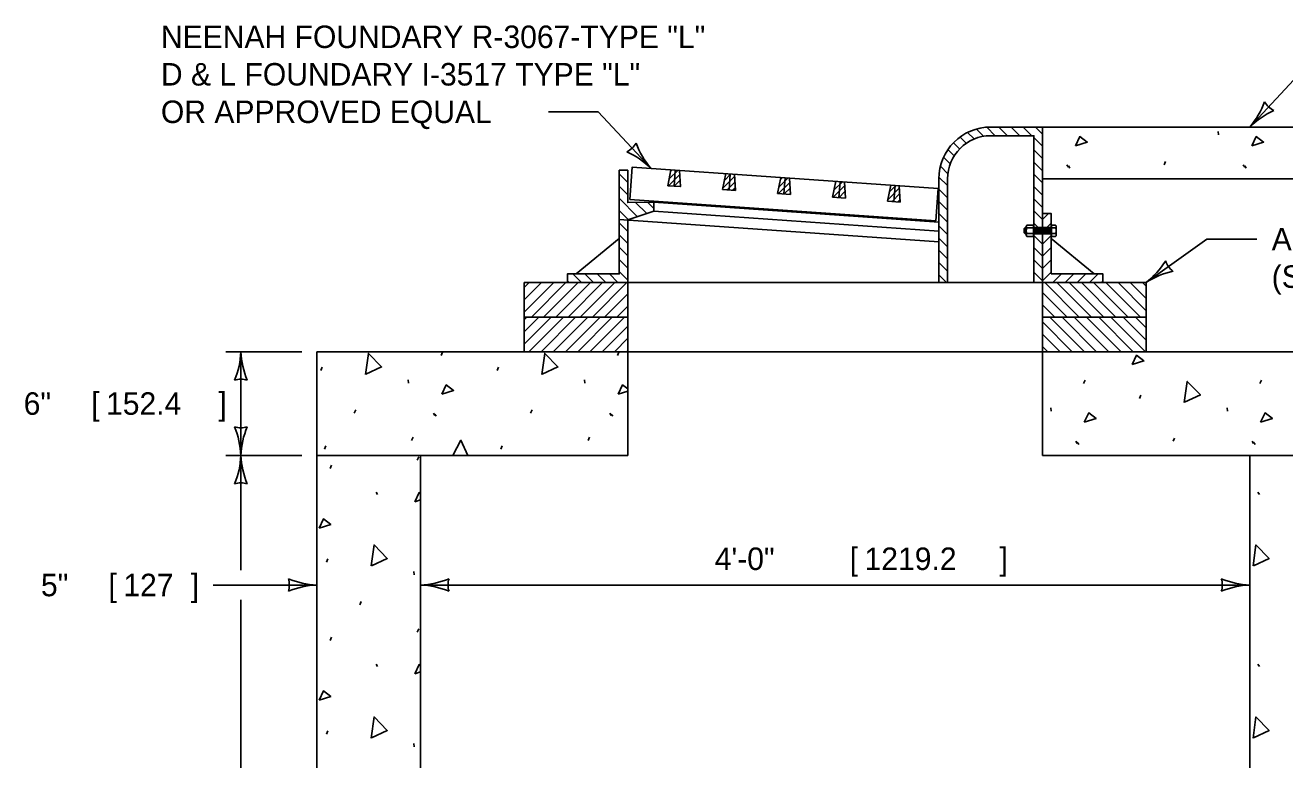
# Model space of a CAD drawing. Extents: x 49991.4 to 50057, y 49987.6 to 50011.4.
# Drawn here: x 50041.919 to 50045.28, y 49991.034 to 49992.994 of the extents above; entities that cross this region are included whole.
import ezdxf

# ---------------------------------------------------------------- set-up
doc = ezdxf.new("R2010")
doc.units = 0
for name, color, linetype in [('Level 1', 7, 'Continuous'), ('Level 2', 7, 'Continuous'), ('Level 3', 7, 'Continuous'), ('Level 4', 7, 'Continuous'), ('Level 5', 7, 'Continuous')]:
    doc.layers.add(name, color=color, linetype=linetype)

msp = doc.modelspace()

# ---------------------------------------------------------------- linework, layer by layer
at = {"layer": 'Level 1'}
for p, q in [((50044.4336, 49992.7076), (50044.451, 49992.6902)), ((50044.4571, 49992.7167), (50044.4763, 49992.6975)), ((50044.4847, 49992.7217), (50044.5074, 49992.699)), ((50044.5169, 49992.722), (50044.54, 49992.699)), ((50044.5495, 49992.722), (50044.5726, 49992.699)), ((50044.5821, 49992.722), (50044.6052, 49992.699)), ((50044.6147, 49992.722), (50044.6334, 49992.7034)), ((50044.6334, 49992.722), (50045.7396, 49992.722)), ((50045.102, 49992.7102), (50045.103, 49992.7014)), ((50044.3959, 49992.6801), (50044.4122, 49992.6638)), ((50044.4133, 49992.6953), (50044.4299, 49992.6788)), ((50044.6103, 49992.6939), (50044.6334, 49992.6708)), ((50044.3694, 49992.6414), (50044.387, 49992.6238)), ((50044.3812, 49992.6622), (50044.3978, 49992.6456)), ((50044.6103, 49992.6613), (50044.6334, 49992.6382)), ((50043.6421, 49992.6082), (50043.6334, 49992.5655)), ((50043.6369, 49992.5828), (50043.661, 49992.6069)), ((50043.6411, 49992.6033), (50043.6458, 49992.608)), ((50043.6651, 49992.6066), (50043.6678, 49992.5631)), ((50044.3609, 49992.6173), (50044.3807, 49992.5976)), ((50044.6103, 49992.6287), (50044.6334, 49992.6056)), ((50044.6985, 49992.6209), (50044.7024, 49992.615)), ((50044.7024, 49992.6187), (50044.7064, 49992.6128)), ((50044.9579, 49992.6209), (50044.9618, 49992.6298)), ((50045.1691, 49992.6209), (50045.173, 49992.615)), ((50045.173, 49992.6187), (50045.1769, 49992.6128)), ((50043.5041, 49992.5973), (50043.5271, 49992.5743)), ((50043.6358, 49992.5654), (50043.6658, 49992.5954)), ((50043.651, 49992.5643), (50043.6668, 49992.5801)), ((50043.7887, 49992.598), (50043.7799, 49992.5553)), ((50043.7807, 49992.5591), (50043.812, 49992.5905)), ((50043.7849, 49992.5796), (50043.8023, 49992.597)), ((50043.7923, 49992.5544), (50043.813, 49992.5751)), ((50043.8117, 49992.5964), (50043.8144, 49992.5529)), ((50043.9352, 49992.5877), (50043.9265, 49992.545)), ((50043.9293, 49992.5448), (50043.959, 49992.5745)), ((50043.9299, 49992.5618), (50043.9545, 49992.5864)), ((50043.9341, 49992.5823), (50043.9393, 49992.5874)), ((50043.9582, 49992.5861), (50043.961, 49992.5426)), ((50044.0818, 49992.5775), (50044.073, 49992.5348)), ((50044.0768, 49992.5533), (50044.0998, 49992.5762)), ((50044.081, 49992.5738), (50044.0846, 49992.5773)), ((50044.1048, 49992.5759), (50044.1075, 49992.5324)), ((50044.3569, 49992.5888), (50044.3799, 49992.5658)), ((50044.6103, 49992.5961), (50044.6334, 49992.573)), ((50044.6334, 49992.5838), (50045.7396, 49992.5838)), ((50043.5041, 49992.5647), (50043.5271, 49992.5417)), ((50043.6334, 49992.5655), (50043.6678, 49992.5631)), ((50043.6662, 49992.5632), (50043.6677, 49992.5648)), ((50043.7799, 49992.5553), (50043.8144, 49992.5529)), ((50043.8075, 49992.5533), (50043.814, 49992.5598)), ((50043.9265, 49992.545), (50043.961, 49992.5426)), ((50043.9445, 49992.5438), (50043.9599, 49992.5592)), ((50043.9597, 49992.5427), (50043.9609, 49992.5438)), ((50044.0745, 49992.5347), (50044.1054, 49992.5656)), ((50044.0898, 49992.5336), (50044.1064, 49992.5502)), ((50044.2284, 49992.5672), (50044.2196, 49992.5245)), ((50044.2204, 49992.5283), (50044.2517, 49992.5597)), ((50044.2246, 49992.5488), (50044.242, 49992.5663)), ((50044.232, 49992.5237), (50044.2527, 49992.5444)), ((50044.2514, 49992.5656), (50044.2541, 49992.5221)), ((50044.3568, 49992.5563), (50044.3799, 49992.5332)), ((50044.6103, 49992.5635), (50044.6334, 49992.5404)), ((50043.5041, 49992.5321), (50043.5532, 49992.483)), ((50043.548, 49992.5208), (50043.5777, 49992.4911)), ((50043.58, 49992.5213), (50043.5963, 49992.5051)), ((50043.5963, 49992.5216), (50043.5963, 49992.5216)), ((50043.5963, 49992.5216), (50044.3568, 49992.4685)), ((50044.073, 49992.5348), (50044.1075, 49992.5324)), ((50044.105, 49992.5325), (50044.1074, 49992.5349)), ((50044.2196, 49992.5245), (50044.2541, 49992.5221)), ((50044.2472, 49992.5226), (50044.2537, 49992.529)), ((50044.3568, 49992.5237), (50044.3799, 49992.5006)), ((50044.6103, 49992.5309), (50044.6334, 49992.5079)), ((50043.5041, 49992.4995), (50043.5288, 49992.4748)), ((50043.5041, 49992.4759), (50044.3568, 49992.4163)), ((50043.5963, 49992.4973), (50044.3568, 49992.4442)), ((50044.3568, 49992.4911), (50044.3799, 49992.468)), ((50044.6103, 49992.4983), (50044.6334, 49992.4753)), ((50044.6334, 49992.4752), (50044.6498, 49992.4916)), ((50043.5041, 49992.4669), (50043.5271, 49992.4439)), ((50044.3568, 49992.4585), (50044.3799, 49992.4354)), ((50044.5841, 49992.4513), (50044.587, 49992.4541)), ((50044.5841, 49992.4513), (50044.5841, 49992.4397)), ((50044.5841, 49992.4397), (50044.587, 49992.4369)), ((50044.5855, 49992.4513), (50044.5855, 49992.4397)), ((50044.587, 49992.4541), (50044.587, 49992.4369)), ((50044.5898, 49992.4541), (50044.587, 49992.4541)), ((50044.5884, 49992.4513), (50044.5884, 49992.4397)), ((50044.5898, 49992.4343), (50044.5898, 49992.4567)), ((50044.6096, 49992.4605), (50044.5918, 49992.4605)), ((50044.6096, 49992.453), (50044.5918, 49992.453)), ((50044.6096, 49992.438), (50044.5918, 49992.438)), ((50044.6096, 49992.4305), (50044.6096, 49992.4605)), ((50044.6103, 49992.4585), (50044.6096, 49992.4585)), ((50044.6103, 49992.4657), (50044.6334, 49992.4427)), ((50044.6103, 49992.4325), (50044.6103, 49992.4585)), ((50044.6334, 49992.4426), (50044.6564, 49992.4656)), ((50044.6564, 49992.4325), (50044.6564, 49992.4585)), ((50044.6564, 49992.4585), (50044.6571, 49992.4585)), ((50044.6571, 49992.4605), (50044.668, 49992.4605)), ((50044.6571, 49992.4305), (50044.6571, 49992.4605)), ((50044.6571, 49992.453), (50044.668, 49992.453)), ((50044.6571, 49992.438), (50044.668, 49992.438)), ((50044.67, 49992.4343), (50044.67, 49992.4567)), ((50043.5041, 49992.4248), (50043.3889, 49992.3303)), ((50043.5041, 49992.4343), (50043.5271, 49992.4113)), ((50044.3568, 49992.4259), (50044.3799, 49992.4028)), ((50044.5898, 49992.4369), (50044.587, 49992.4369)), ((50044.6096, 49992.4305), (50044.5918, 49992.4305)), ((50044.6103, 49992.4325), (50044.6096, 49992.4325)), ((50044.6103, 49992.4331), (50044.6334, 49992.4101)), ((50044.6334, 49992.41), (50044.6564, 49992.4331)), ((50044.6564, 49992.4325), (50044.6571, 49992.4325)), ((50044.6564, 49992.4248), (50044.7716, 49992.3303)), ((50044.6571, 49992.4305), (50044.668, 49992.4305)), ((50043.5041, 49992.4017), (50043.5271, 49992.3787)), ((50044.3568, 49992.3933), (50044.3799, 49992.3703)), ((50044.6103, 49992.4005), (50044.6334, 49992.3775)), ((50044.6334, 49992.3774), (50044.6564, 49992.4005)), ((50043.5041, 49992.3692), (50043.5271, 49992.3461)), ((50044.3568, 49992.3607), (50044.3799, 49992.3377)), ((50044.6103, 49992.3679), (50044.6334, 49992.3449)), ((50044.6334, 49992.3448), (50044.6564, 49992.3679)), ((50043.2506, 49992.2285), (50043.3293, 49992.3072)), ((50043.2506, 49992.2611), (50043.2967, 49992.3072)), ((50043.2506, 49992.2937), (50043.2641, 49992.3072)), ((50043.2697, 49992.215), (50043.3619, 49992.3072)), ((50043.3023, 49992.215), (50043.3945, 49992.3072)), ((50043.3349, 49992.215), (50043.4271, 49992.3072)), ((50043.3658, 49992.3119), (50043.3705, 49992.3072)), ((50043.3658, 49992.3119), (50043.3705, 49992.3072)), ((50043.3675, 49992.215), (50043.4596, 49992.3072)), ((50043.38, 49992.3303), (50043.4031, 49992.3072)), ((50043.4001, 49992.215), (50043.4922, 49992.3072)), ((50043.4126, 49992.3303), (50043.4357, 49992.3072)), ((50043.4326, 49992.215), (50043.5248, 49992.3072)), ((50043.4452, 49992.3303), (50043.4683, 49992.3072)), ((50043.4778, 49992.3303), (50043.5008, 49992.3072)), ((50043.5041, 49992.3366), (50043.5271, 49992.3135)), ((50043.5271, 49992.3072), (50044.6334, 49992.3072)), ((50043.5271, 49992.3072), (50044.6334, 49992.3072)), ((50044.3568, 49992.3281), (50044.3777, 49992.3072)), ((50044.6103, 49992.3353), (50044.6334, 49992.3123)), ((50044.6334, 49992.3122), (50044.6564, 49992.3353)), ((50044.6394, 49992.3072), (50044.7316, 49992.215)), ((50044.6609, 49992.3072), (50044.684, 49992.3303)), ((50044.672, 49992.3072), (50044.7642, 49992.215)), ((50044.6935, 49992.3072), (50044.7166, 49992.3303)), ((50044.7046, 49992.3072), (50044.7968, 49992.215)), ((50044.7261, 49992.3072), (50044.7492, 49992.3303)), ((50044.7372, 49992.3072), (50044.8294, 49992.215)), ((50044.7587, 49992.3072), (50044.7818, 49992.3303)), ((50044.7698, 49992.3072), (50044.862, 49992.215)), ((50044.7913, 49992.3072), (50044.7947, 49992.3106)), ((50044.7913, 49992.3072), (50044.7947, 49992.3106)), ((50044.8024, 49992.3072), (50044.8946, 49992.215)), ((50044.835, 49992.3072), (50044.9099, 49992.2323)), ((50044.8676, 49992.3072), (50044.9099, 49992.2649)), ((50044.9002, 49992.3072), (50044.9099, 49992.2975)), ((50043.4652, 49992.215), (50043.5271, 49992.2769)), ((50044.6334, 49992.2807), (50044.699, 49992.215)), ((50043.4978, 49992.215), (50043.5271, 49992.2444)), ((50044.6334, 49992.2481), (50044.6664, 49992.215)), ((50043.2506, 49992.143), (50043.3227, 49992.215)), ((50043.2506, 49992.1756), (50043.2901, 49992.215)), ((50043.2506, 49992.2082), (50043.2575, 49992.215)), ((50043.2631, 49992.1229), (50043.3552, 49992.215)), ((50043.2957, 49992.1229), (50043.3878, 49992.215)), ((50043.3282, 49992.1229), (50043.4204, 49992.215)), ((50043.3608, 49992.1229), (50043.453, 49992.215)), ((50043.3934, 49992.1229), (50043.4856, 49992.215)), ((50043.426, 49992.1229), (50043.5182, 49992.215)), ((50044.6334, 49992.2155), (50044.6339, 49992.215)), ((50044.6531, 49992.215), (50044.7453, 49992.1229)), ((50044.6857, 49992.215), (50044.7778, 49992.1229)), ((50044.7183, 49992.215), (50044.8104, 49992.1229)), ((50044.7508, 49992.215), (50044.843, 49992.1229)), ((50044.7834, 49992.215), (50044.8756, 49992.1229)), ((50044.816, 49992.215), (50044.9082, 49992.1229)), ((50044.8486, 49992.215), (50044.9099, 49992.1537)), ((50044.8812, 49992.215), (50044.9099, 49992.1863)), ((50043.4586, 49992.1229), (50043.5271, 49992.1914)), ((50044.6334, 49992.2022), (50044.7127, 49992.1229)), ((50044.6334, 49992.1696), (50044.6801, 49992.1229)), ((50043.4912, 49992.1229), (50043.5271, 49992.1588)), ((50044.6334, 49992.137), (50044.6475, 49992.1229)), ((50042.6975, 49989.6339), (50042.6975, 49992.1229)), ((50042.6975, 49992.1229), (50043.5271, 49992.1229)), ((50043.029, 49992.1128), (50043.0329, 49992.1217)), ((50043.4995, 49992.1128), (50043.5035, 49992.1217)), ((50043.5238, 49992.1229), (50043.5271, 49992.1262)), ((50043.5271, 49992.1229), (50043.5271, 49991.8463)), ((50043.5271, 49992.1229), (50044.6334, 49992.1229)), ((50044.6334, 49992.1229), (50045.463, 49992.1229)), ((50044.6334, 49992.1229), (50044.6334, 49991.8463)), ((50042.7077, 49992.0725), (50042.7117, 49992.0814)), ((50043.1783, 49992.0725), (50043.1822, 49992.0814)), ((50042.9413, 49992.0479), (50042.9423, 49992.039)), ((50043.4119, 49992.0479), (50043.4128, 49992.039)), ((50044.7429, 49992.038), (50044.7468, 49992.0468)), ((50045.2134, 49992.038), (50045.2173, 49992.0468)), ((50043.5271, 49992.0177), (50043.5015, 49992.0097)), ((50044.8922, 49991.9977), (50044.8961, 49992.0066)), ((50042.7971, 49991.9586), (50042.8011, 49991.9674)), ((50043.2677, 49991.9586), (50043.2716, 49991.9674)), ((50044.6552, 49991.973), (50044.6562, 49991.9642)), ((50045.1257, 49991.973), (50045.1267, 49991.9642)), ((50043.0084, 49991.9586), (50043.0123, 49991.9527)), ((50043.0123, 49991.9564), (50043.0162, 49991.9505)), ((50043.4789, 49991.9586), (50043.4828, 49991.9527)), ((50043.4828, 49991.9564), (50043.4868, 49991.9505)), ((50042.7176, 49991.8632), (50042.7215, 49991.872)), ((50042.9504, 49991.8858), (50042.9543, 49991.8946)), ((50043.1881, 49991.8632), (50043.1921, 49991.872)), ((50043.4209, 49991.8858), (50043.4249, 49991.8946)), ((50044.7222, 49991.8838), (50044.7261, 49991.8779)), ((50044.7261, 49991.8815), (50044.7301, 49991.8756)), ((50044.9816, 49991.8838), (50044.9855, 49991.8926)), ((50045.1928, 49991.8838), (50045.1967, 49991.8779)), ((50045.1967, 49991.8815), (50045.2006, 49991.8756)), ((50042.6975, 49991.8463), (50043.5271, 49991.8463)), ((50042.9654, 49991.8337), (50042.9693, 49991.8425)), ((50042.974, 49989.9104), (50042.974, 49991.8463)), ((50044.6334, 49991.8463), (50045.463, 49991.8463)), ((50045.1865, 49989.9104), (50045.1865, 49991.8463)), ((50042.7326, 49991.8111), (50042.7365, 49991.8199)), ((50042.8554, 49991.7482), (50042.8593, 49991.7423)), ((50045.2081, 49991.7482), (50045.2121, 49991.7423)), ((50042.974, 49991.7275), (50042.9585, 49991.7227)), ((50042.7228, 49991.5616), (50042.7267, 49991.5704)), ((50042.9563, 49991.5369), (50042.9573, 49991.5281)), ((50042.8121, 49991.4476), (50042.8161, 49991.4565)), ((50042.9654, 49991.3748), (50042.9693, 49991.3837)), ((50042.7326, 49991.3522), (50042.7365, 49991.3611)), ((50042.8554, 49991.2893), (50042.8593, 49991.2835)), ((50042.974, 49991.2687), (50042.9585, 49991.2638)), ((50045.2081, 49991.2893), (50045.2121, 49991.2835)), ((50042.7228, 49991.1027), (50042.7267, 49991.1115)), ((50042.9563, 49991.078), (50042.9573, 49991.0692))]:
    msp.add_line(p, q, dxfattribs=at)
for points in [[(50044.4951, 49992.699), (50044.6103, 49992.699), (50044.6103, 49992.3072), (50044.6334, 49992.3072), (50044.6334, 49992.722), (50044.4951, 49992.722)], [(50044.7211, 49992.672), (50044.7329, 49992.6966), (50044.7526, 49992.6818), (50044.7211, 49992.672)], [(50045.1917, 49992.672), (50045.2035, 49992.6966), (50045.2231, 49992.6818), (50045.1917, 49992.672)], [(50044.3568, 49992.5838), (50044.3568, 49992.3072), (50044.3799, 49992.3072), (50044.3799, 49992.5838)], [(50042.8273, 49992.0624), (50042.835, 49992.1185), (50042.8702, 49992.0822), (50042.8282, 49992.0627)], [(50043.2978, 49992.0624), (50043.3056, 49992.1185), (50043.3408, 49992.0822), (50043.2987, 49992.0627)], [(50044.8727, 49992.0886), (50044.8845, 49992.1132), (50044.9041, 49992.0984), (50044.8727, 49992.0886)], [(50045.0117, 49991.9875), (50045.0195, 49992.0437), (50045.0546, 49992.0074), (50045.0126, 49991.9879)], [(50043.031, 49992.0097), (50043.0427, 49992.0342), (50043.0624, 49992.0195), (50043.031, 49992.0097)], [(50043.5015, 49992.0097), (50043.5133, 49992.0342), (50043.5271, 49992.0239)], [(50044.7448, 49991.9348), (50044.7566, 49991.9594), (50044.7763, 49991.9447), (50044.7448, 49991.9348)], [(50045.2154, 49991.9348), (50045.2272, 49991.9594), (50045.2468, 49991.9447), (50045.2154, 49991.9348)], [(50043.0606, 49991.8463), (50043.082, 49991.8868), (50043.1001, 49991.8463)], [(50042.9585, 49991.7227), (50042.9703, 49991.7472), (50042.974, 49991.7444)], [(50042.7033, 49991.6525), (50042.7151, 49991.677), (50042.7347, 49991.6623), (50042.7033, 49991.6525)], [(50042.8423, 49991.5514), (50042.8501, 49991.6076), (50042.8852, 49991.5712), (50042.8432, 49991.5517)], [(50045.195, 49991.5514), (50045.2028, 49991.6076), (50045.238, 49991.5712), (50045.196, 49991.5517)], [(50042.9585, 49991.2638), (50042.9703, 49991.2884), (50042.974, 49991.2856)], [(50042.7033, 49991.1936), (50042.7151, 49991.2181), (50042.7347, 49991.2034), (50042.7033, 49991.1936)], [(50042.8423, 49991.0925), (50042.8501, 49991.1487), (50042.8852, 49991.1124), (50042.8432, 49991.0929)], [(50045.195, 49991.0925), (50045.2028, 49991.1487), (50045.238, 49991.1124), (50045.196, 49991.0929)]]:
    msp.add_lwpolyline(points, dxfattribs=at)
for points in [[(50043.5271, 49992.4743), (50043.5271, 49992.3072), (50043.3658, 49992.3072), (50043.3658, 49992.3303), (50043.5041, 49992.3303), (50043.5041, 49992.6068), (50043.5271, 49992.6068), (50043.5271, 49992.5204), (50043.5963, 49992.5216), (50043.5963, 49992.4973)], [(50044.3548, 49992.5584), (50043.5387, 49992.6155), (50043.5326, 49992.5292), (50044.3488, 49992.4722)], [(50044.6564, 49992.3303), (50044.6564, 49992.4916), (50044.6334, 49992.4916), (50044.6334, 49992.3072), (50044.7947, 49992.3072), (50044.7947, 49992.3303)], [(50043.2506, 49992.3072), (50043.5271, 49992.3072), (50043.5271, 49992.215), (50043.2506, 49992.215)], [(50044.6334, 49992.3072), (50044.9099, 49992.3072), (50044.9099, 49992.215), (50044.6334, 49992.215)], [(50043.2506, 49992.215), (50043.5271, 49992.215), (50043.5271, 49992.1229), (50043.2506, 49992.1229)], [(50044.6334, 49992.215), (50044.9099, 49992.215), (50044.9099, 49992.1229), (50044.6334, 49992.1229)]]:
    msp.add_lwpolyline(points, close=True, dxfattribs=at)
for centre, radius, start, end in [((50044.4951, 49992.5838), 0.1383, 90, 180), ((50044.4951, 49992.5838), 0.1152, 90, 180), ((50044.5943, 49992.4567), 0.0045, 123.6844, 236.3156), ((50044.6048, 49992.4455), 0.015, 150.0207, 209.9793), ((50044.5943, 49992.4343), 0.00449, 123.6376, 236.3624), ((50044.6655, 49992.4567), 0.0045, 303.6844, 56.3156), ((50044.655, 49992.4455), 0.015, 330.0207, 29.9793), ((50044.6655, 49992.4343), 0.00449, 303.6376, 56.3624)]:
    msp.add_arc(centre, radius, start, end, dxfattribs=at)
at = {"layer": 'Level 3'}
for p, q in [((50045.1865, 49992.722), (50045.3269, 49992.8729)), ((50045.1865, 49992.722), (50045.3269, 49992.8729)), ((50043.3154, 49992.7628), (50043.4482, 49992.7628)), ((50043.5886, 49992.612), (50043.4482, 49992.7628)), ((50044.9099, 49992.3072), (50045.0721, 49992.4231)), ((50045.2048, 49992.4231), (50045.0721, 49992.4231)), ((50042.6575, 49992.1229), (50042.4548, 49992.1229)), ((50042.4948, 49992.1229), (50042.4948, 49991.8463)), ((50042.6575, 49991.8463), (50042.4548, 49991.8463)), ((50042.4948, 49991.5406), (50042.4948, 49991.8463)), ((50042.6975, 49991.5006), (50042.4209, 49991.5006)), ((50042.974, 49991.5006), (50045.1865, 49991.5006)), ((50042.4948, 49989.9104), (50042.4948, 49991.4606))]:
    msp.add_line(p, q, dxfattribs=at)
for centre, radius, start, end in [((50045.0083, 49992.8722), 0.233, 319.8832, 339.1331), ((50045.0083, 49992.8722), 0.233, 319.8832, 339.1331), ((50045.2738, 49992.8159), 0.0548, 209.1947, 244.9171), ((50045.2738, 49992.8159), 0.0548, 209.1947, 244.9171), ((50045.3428, 49992.564), 0.2223, 114.5119, 134.6954), ((50045.3428, 49992.564), 0.2223, 114.5119, 134.6954), ((50043.5012, 49992.7058), 0.0548, 295.0829, 330.8053), ((50043.7667, 49992.7621), 0.233, 200.8669, 220.1168), ((50043.4322, 49992.4539), 0.2223, 45.3046, 65.4881), ((50044.7652, 49992.4899), 0.233, 308.3805, 327.6303), ((50045.0316, 49992.1212), 0.2223, 103.0092, 123.1927), ((50045.0142, 49992.3818), 0.0548, 197.692, 233.4143), ((50042.2727, 49992.132), 0.2223, 337.456, 357.6395), ((50042.7275, 49992.1343), 0.233, 182.8273, 202.0772), ((50042.4948, 49991.9946), 0.0548, 72.1388, 107.8612), ((50042.4948, 49991.9745), 0.0548, 252.1388, 287.8612), ((50042.2621, 49991.8348), 0.233, 2.8273, 22.0772), ((50042.7169, 49991.8371), 0.2223, 157.456, 177.6395), ((50042.2727, 49991.8555), 0.2223, 337.456, 357.6395), ((50042.7275, 49991.8578), 0.233, 182.8273, 202.0772), ((50042.4948, 49991.7181), 0.0548, 72.1388, 107.8612), ((50042.7066, 49991.7227), 0.2223, 247.456, 267.6395), ((50042.5693, 49991.5006), 0.0548, 342.1388, 17.8612), ((50042.709, 49991.2679), 0.233, 92.8273, 112.0772), ((50042.9625, 49991.7333), 0.233, 272.8273, 292.0772), ((50042.9649, 49991.2785), 0.2223, 67.456, 87.6395), ((50043.1023, 49991.5006), 0.0548, 162.1388, 197.8612), ((50045.1956, 49991.7227), 0.2223, 247.456, 267.6395), ((50045.0582, 49991.5006), 0.0548, 342.1388, 17.8612), ((50045.198, 49991.2679), 0.233, 92.8273, 112.0772)]:
    msp.add_arc(centre, radius, start, end, dxfattribs=at)
at = {"layer": 'Level 4'}
for p, q in [((50044.6564, 49992.4541), (50044.6103, 49992.4541)), ((50044.6114, 49992.4513), (50044.6114, 49992.4397)), ((50044.6129, 49992.4541), (50044.6129, 49992.4369)), ((50044.6143, 49992.4513), (50044.6143, 49992.4397)), ((50044.6158, 49992.4541), (50044.6158, 49992.4369)), ((50044.6172, 49992.4513), (50044.6172, 49992.4397)), ((50044.6186, 49992.4541), (50044.6186, 49992.4369)), ((50044.6201, 49992.4513), (50044.6201, 49992.4397)), ((50044.6215, 49992.4541), (50044.6215, 49992.4369)), ((50044.623, 49992.4513), (50044.623, 49992.4397)), ((50044.6244, 49992.4541), (50044.6244, 49992.4369)), ((50044.6258, 49992.4513), (50044.6258, 49992.4397)), ((50044.6273, 49992.4541), (50044.6273, 49992.4369)), ((50044.6287, 49992.4513), (50044.6287, 49992.4397)), ((50044.6302, 49992.4541), (50044.6302, 49992.4369)), ((50044.6316, 49992.4513), (50044.6316, 49992.4397)), ((50044.633, 49992.4541), (50044.633, 49992.4369)), ((50044.6345, 49992.4513), (50044.6345, 49992.4397)), ((50044.6359, 49992.4541), (50044.6359, 49992.4369)), ((50044.6374, 49992.4513), (50044.6374, 49992.4397)), ((50044.6388, 49992.4541), (50044.6388, 49992.4369)), ((50044.6402, 49992.4513), (50044.6402, 49992.4397)), ((50044.6417, 49992.4541), (50044.6417, 49992.4369)), ((50044.6431, 49992.4513), (50044.6431, 49992.4397)), ((50044.6446, 49992.4541), (50044.6446, 49992.4369)), ((50044.646, 49992.4513), (50044.646, 49992.4397)), ((50044.6474, 49992.4541), (50044.6474, 49992.4369)), ((50044.6489, 49992.4513), (50044.6489, 49992.4397)), ((50044.6503, 49992.4541), (50044.6503, 49992.4369)), ((50044.6518, 49992.4513), (50044.6518, 49992.4397)), ((50044.6532, 49992.4541), (50044.6532, 49992.4369)), ((50044.6547, 49992.4513), (50044.6547, 49992.4397)), ((50044.6564, 49992.4369), (50044.6103, 49992.4369))]:
    msp.add_line(p, q, dxfattribs=at)
at = {"layer": 'Level 5'}
for p, q in [((50043.6536, 49992.6074), (50043.6506, 49992.5643)), ((50043.8002, 49992.5972), (50043.7972, 49992.5541)), ((50043.9467, 49992.5869), (50043.9437, 49992.5438)), ((50044.0933, 49992.5767), (50044.0903, 49992.5336)), ((50044.2399, 49992.5664), (50044.2368, 49992.5233))]:
    msp.add_line(p, q, dxfattribs=at)

# ---------------------------------------------------------------- texts
at = {"layer": 'Level 2'}
for s, p in [('ADJUSTING RINGS AS NEEDED', (50045.2448, 49992.3931)), ('(SEE DTL. DWG. 621-00)', (50045.2448, 49992.2931)), ('6" ', (50041.9153, 49991.9546)), ('[', (50042.0953, 49991.9546)), ('152.4', (50042.135, 49991.9546)), (']', (50042.435, 49991.9546)), ('4\'-0" ', (50043.759, 49991.5406)), ('[', (50044.119, 49991.5406)), ('1219.2', (50044.1587, 49991.5406)), (']', (50044.5187, 49991.5406)), ('5" ', (50041.9614, 49991.4706)), ('[', (50042.1414, 49991.4706)), ('127', (50042.1811, 49991.4706)), (']', (50042.3611, 49991.4706))]:
    msp.add_text(s, height=0.06, dxfattribs=at).set_placement(p)
at = {"layer": 'Level 3'}
for s, p in [('NEENAH FOUNDARY R-3067-TYPE "L"', (50042.2814, 49992.9328)), ('D & L FOUNDARY I-3517 TYPE "L"', (50042.2814, 49992.8328)), ('OR APPROVED EQUAL', (50042.2814, 49992.7328))]:
    msp.add_text(s, height=0.06, dxfattribs=at).set_placement(p)

doc.saveas('drawing.dxf')
